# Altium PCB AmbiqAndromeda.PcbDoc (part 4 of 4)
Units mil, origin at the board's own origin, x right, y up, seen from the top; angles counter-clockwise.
Board outline 4055.04 x 2407.2 mil, 6 copper layers (Layer 1, Layer 2, Layer 3, Layer 4, Layer 5, Layer 6), stack 76.457 mil thick; 255 components, 215 nets, 1186 pads, 683 vias.
Unrouted connection lines stored in the file: 258.
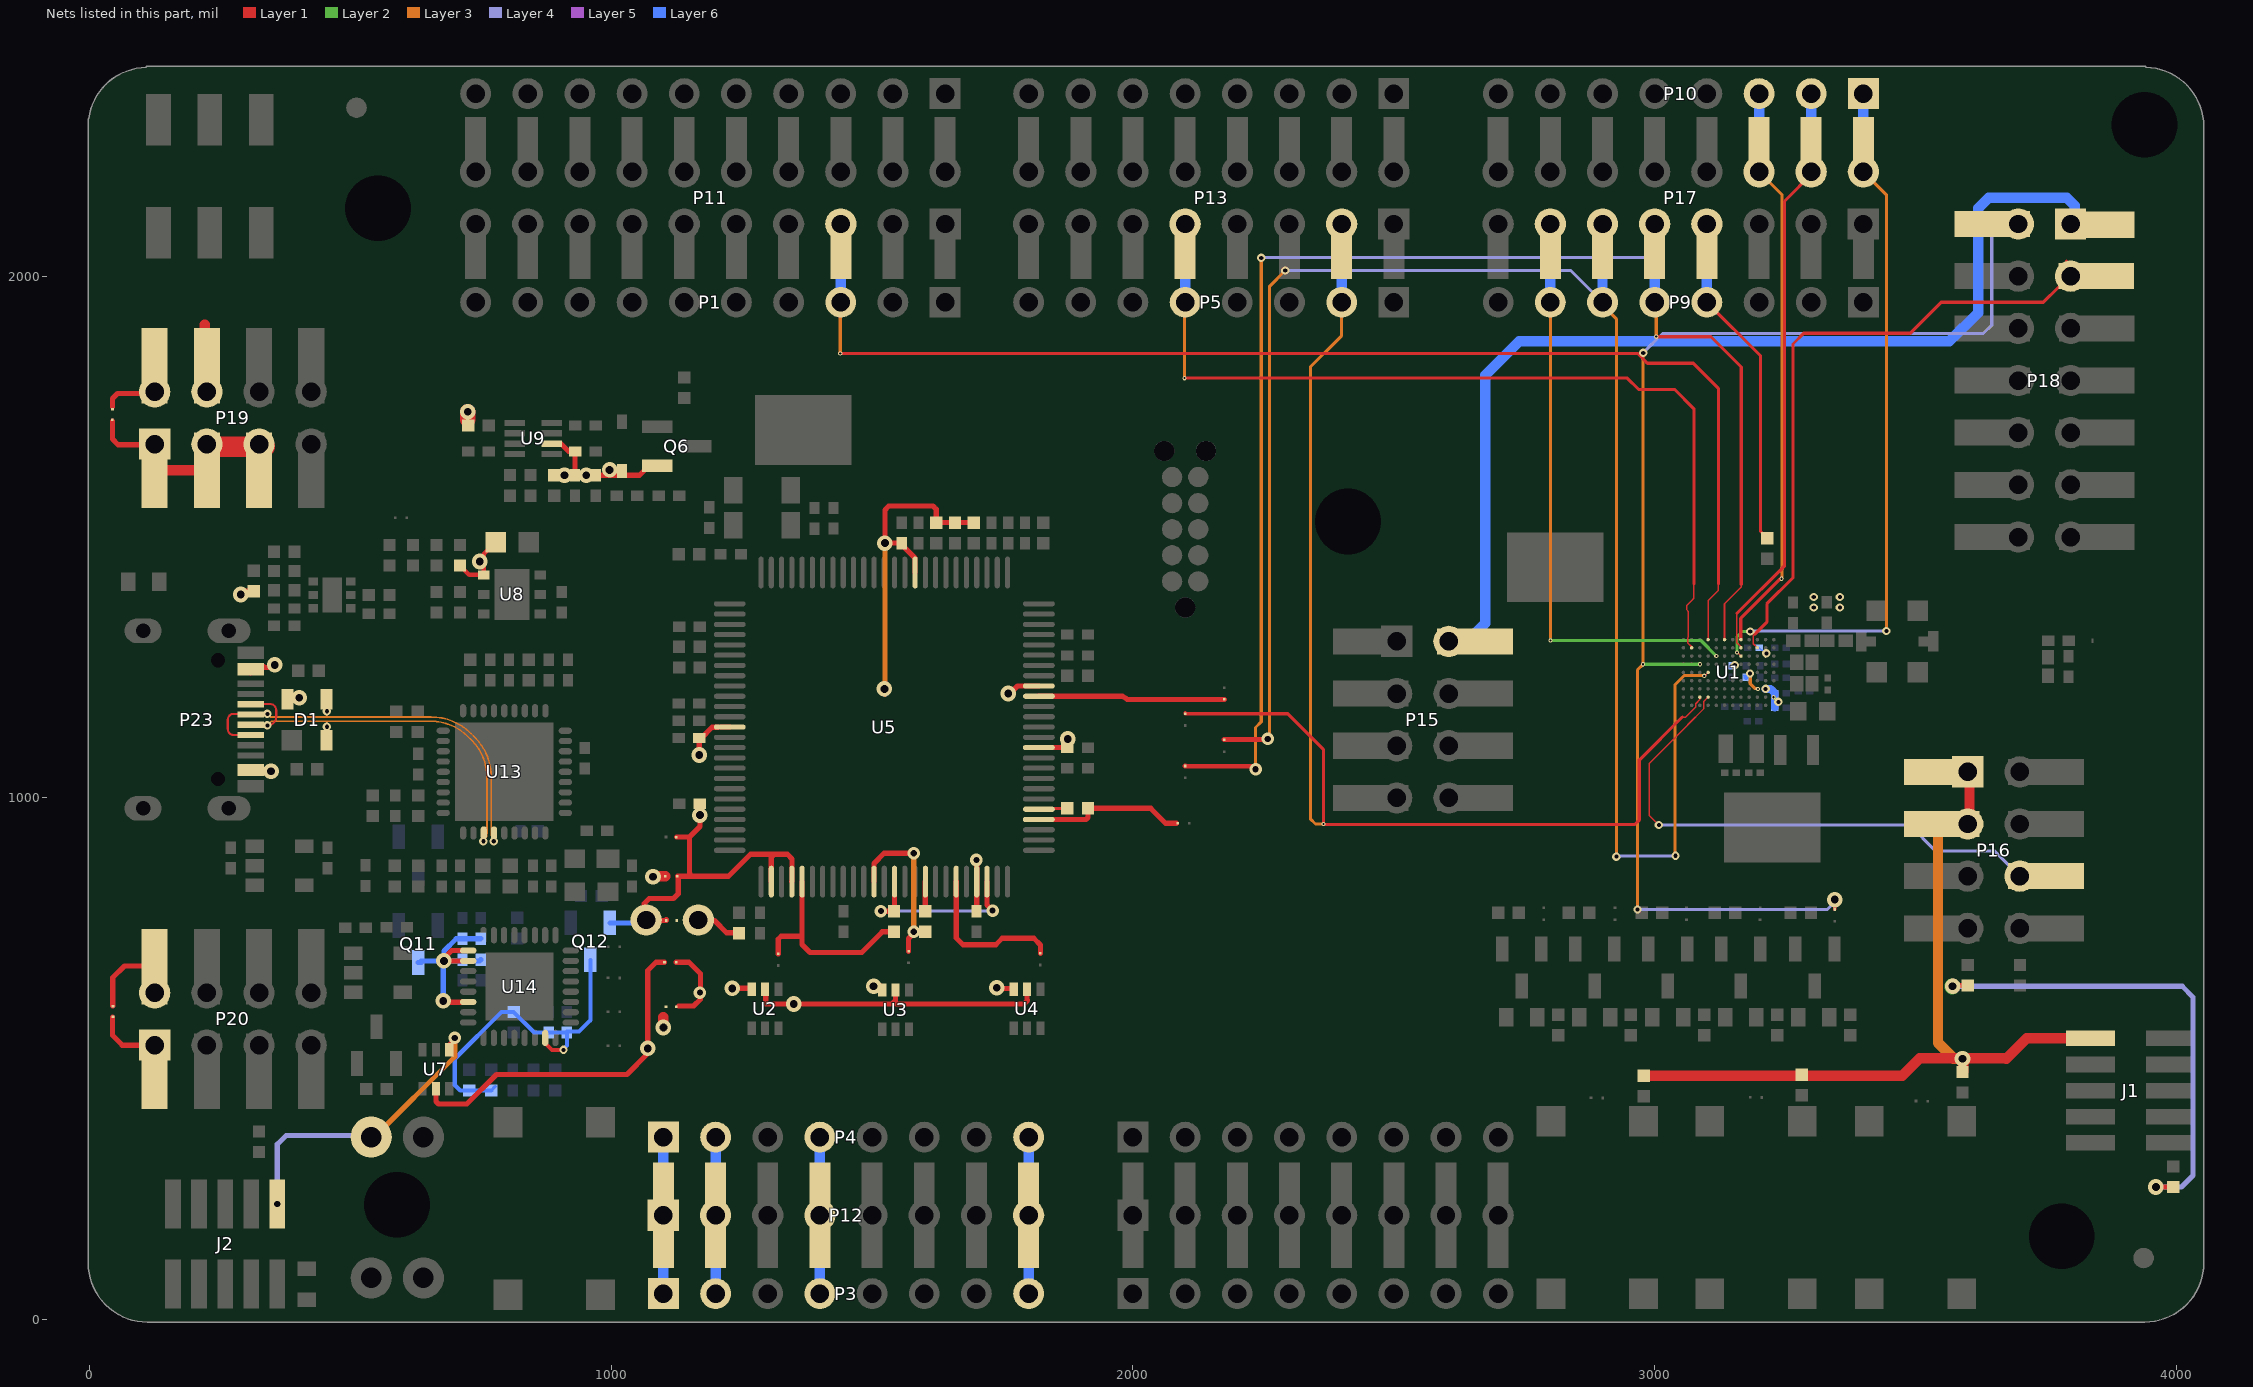
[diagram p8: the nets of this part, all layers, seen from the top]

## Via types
v1: diameter 30, hole 15, Layer 1 to Layer 6, tented both sides, 227 vias
v2: diameter 8, hole 4, Layer 1 to Layer 2, tented both sides, 113 vias
v3: diameter 8, hole 4, Layer 2 to Layer 3, tented both sides, 98 vias
v4: diameter 24, hole 12, Layer 1 to Layer 6, tented both sides, 91 vias
v5: diameter 16, hole 8, Layer 3 to Layer 4, tented both sides, 71 vias
v6: diameter 8, hole 4, Layer 5 to Layer 6, tented both sides, 26 vias
v7: diameter 16, hole 8, Layer 1 to Layer 6, tented both sides, 25 vias
v8: diameter 8, hole 4, Layer 4 to Layer 5, tented both sides, 20 vias
v9: diameter 8, hole 4, Layer 1 to Layer 2, 4 vias
v10: diameter 8, hole 4, Layer 2 to Layer 3, 4 vias
v11: diameter 16/16/16/16/16/16 (per signal layer), hole 8, Layer 1 to Layer 6, tented both sides, 2 vias
v12: diameter 24/0/0/24/24/24 (per signal layer), hole 12, Layer 1 to Layer 6, tented both sides, 1 vias
v13: diameter 30/0/0/30/30/30 (per signal layer), hole 15, Layer 1 to Layer 6, tented both sides, 1 vias

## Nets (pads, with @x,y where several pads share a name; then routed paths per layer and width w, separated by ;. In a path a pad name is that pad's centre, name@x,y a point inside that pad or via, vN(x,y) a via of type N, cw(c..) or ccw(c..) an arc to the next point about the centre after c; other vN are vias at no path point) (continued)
SWO_NCE71_CT21_TX0_RX0_TX1_RX1_GP71: P10.3 P17.6 U1.J5 | length 1112.9
  Layer 1 w3: U1.J5@3164.99,1303.77 U1.J5@3165.32,1303.45
  Layer 1 w6: U1.J5@3164.99,1303.77 3164.99,1344.14 3240.86,1420 v2(3242.93,1420)
  Layer 3 w6: P17.6@3200,2200 3244,2156 v3@3244,1420
  Layer 6 w6: P17.6@3200,2200 P17.6@3214.51,2200
  Layer 6 w20: P17.6@3200,2200 P10.3@3200,2349.99
  other v3: 3242.93,1420
SWO_NCE72_CT22_TX0_RX0_TX1_RX1_GP72: P10.2 P17.4 U1.H5 | length 1150.5
  Layer 1 w3: 3157.49,1353.49 3157.49,1312.02 3157.47,1297.53 3163.76,1291.24 3163.76,1290.25 3165.32,1288.7 U1.H5@3165.32,1287.7
  Layer 1 w6: 3157.49,1353.49 3249,1445 3249,2144 3305,2200 P17.4@3300,2200
  Layer 6 w6: P17.4@3300,2200 P17.4@3305,2200
  Layer 6 w10: P17.4@3289,2203 3292,2200 P17.4@3300,2200
  Layer 6 w20: P17.4@3289,2203 3300,2214 P10.2@3300,2349.99
SWO_NCE73_CT23_CTS0_RTS0_CTS1_RTS1_GP73: P10.1 P17.2 U1.G5 | length 1387.7
  Layer 1 w3: v2(3158,1279) 3158.27,1279 U1.G5@3165.32,1271.95
  Layer 2 w3: v2@3157.46,1279 v2(3158,1279)
  Layer 2 w6: v2@3157.46,1279 3157.46,1308.46 3168,1319 v3(3183,1319)
  Layer 3 w6: P17.2@3400,2200 3444,2156 v5(3444,1320)
  Layer 4 w6: v3(3183,1319) 3184,1320 v5(3444,1320)
  Layer 6 w6: P10.1@3400,2349.99 3405.01,2349.99 P10.1@3406,2349
  Layer 6 w20: P17.2@3400,2200 3400,2343 P10.1@3406,2349
  other v5: 3183,1319
TCKin: R6.1 SB7.1 U5.5 | length 395.4
  Layer 1 w10: SB7.1@1320,701.19 1320,729.14 1325.86,735 1365.89,735 ; U5.5@1365.89,839.53 1365.89,735 ; R6.1@1542,743.32 1519.57,743.32 1480.18,703.93 1381.07,703.93 1365.89,719.11 1365.89,735
TCKout: R6.2 U5.14 U5.23 | length 352.2
  Layer 1 w10: v4@1523.37,783.74 1524.42,782.69 R6.2@1542,782.69 1543.05,783.74 U5.14@1543.05,839.53 ; U5.23@1720.22,839.53 1720.22,794.78 v4(1731,784)
  Layer 5 w10: v4@1730.21,783.21 v4(1731,784) v4@1732,785
  Layer 4 w6: v4(1516.9,783.21) v4@1730.21,783.21
TDOin: SB10.1 U5.20 | length 301.6
  Layer 1 w10: U5.20@1661.17,839.53 1661.17,731.3 1673.98,718.48 1736.98,718.48 1749.57,731.07 1809.93,731.07 1823,718 ; SB10.1@1822.57,702.18 1822.57,717.77
TMSin: R7.1 SB8.1 U5.12 | length 334.4
  Layer 1 w10: U5.12@1503.68,839.53 1503.68,874.55 1523.14,894 v4(1580,894) ; SB8.1@1570,706.19 1570,730.46 1579.68,740.14 v4(1579.68,743.32) R7.1@1602,743.32
  Layer 3 w10: v4(1579.68,743.32) v4@1579.68,894.89
TMSout: R7.2 U5.17 | length 56.9
  Layer 1 w10: R7.2@1602,782.69 1602,839.42 U5.17@1602.11,839.53
TRESin: R9.1 SB9.1 U5.29 | length 295.2
  Layer 1 w10: U5.29@1819.63,958.62 1910.12,958.62 1913.68,962.19 R9.1@1913.68,980 2034,980 2062.49,951.51 SB9.1@2083.7,951.51
TRESout: R9.2 U5.30 | length 55.4
  Layer 1 w6: U5.30@1819.63,978.31 1822.61,978.31 1824.3,980 R9.2@1874.31,980
TRG1_NCE36_RX1_32K_CTS1_CTS0_PDMD_GP36: P9.7 P17.13 U1.G8 | length 1133.2
  Layer 1 w6: P9.7@2800,1950 P9.7@2802.02,1947.98
  Layer 2 w6: v3(2800,1302) 2800,1303 2800.5,1303.5 2802,1302 3088.02,1302 v2(3118.07,1271.95)
  Layer 3 w6: v3(2800,1302) P9.7@2800,1950
  Layer 6 w10: P9.7@2800,1950 P9.7@2800,1966
  Layer 6 w20: P9.7@2800,1966 P17.13@2800,2100
TRG2_NCE37_RTS0_SCCIO_TX1_PDMC_CT29_GP37: P9.6 P17.11 SB13.2 U1.E9 | length 3383
  Layer 1 w3: v2(3095,1234) 3095.87,1234 U1.E9@3102.33,1240.45 U1.E9@3103.03,1241.16
  Layer 1 w6: P17.11@2891.31,2103 2894.31,2100 P17.11@2900,2100
  Layer 1 w10: SB13.2@2174.63,1111.85 v4@2256.53,1111.85
  Layer 2 w3: v2(3095,1234) v3@3095.87,1234
  Layer 3 w6: v4(2258.24,1113) 2262,1116.76 2262,1981 v5(2292,2011) ; P9.6@2900,1950 2900,1944.69 2926.5,1918.19 v5(2926.5,887.5) ; v5(3040,889) 3039,890 3039,1217 3056.71,1234.71 3094.29,1234.71 v2(3095,1234)
  Layer 4 w6: v5(2292,2011) 2839,2011 P9.6@2900,1950 ; v5(2926.5,887.5) 2929,885 2931,887 2932,886 2935,889 v5(3040,889)
  Layer 6 w20: P9.6@2900,1950 P17.11@2900,2100 P17.11@2900,2101.5
  other v3: 3095,1234
TRIG3_NCE38_CTS0_M3MOSI_RX1_GP38: P9.5 P17.9 SB14.2 U1.J7 | length 2878.9
  Layer 1 w3: U1.J7@3133.82,1303.45 3133.82,1372 3166,1404.18 3166,1409
  Layer 1 w6: v2(3003,1884) 3108,1884 3166,1826 3166,1409
  Layer 1 w10: SB14.2@2100.12,1061.19 2230.14,1059.95 v4(2235,1055)
  Layer 5 w10: P17.9@3000,2100 P17.9@3003,2097
  Layer 3 w3: P9.5@2999,1944 3000,1945 P9.5@3000,1950
  Layer 3 w6: v4(2235,1055) 2235,1135 2246,1146 v5(2246,2035) ; P9.5@3000,1950 3003,1947 v2(3003,1884)
  Layer 4 w6: v5@2246,2036 2983,2036 3003,2056 P17.9@3003,2097
  Layer 6 w3: P9.5@3000,1950 P9.5@3000.33,1950
  Layer 6 w20: P9.5@3000,1950 P17.9@3000,2100
  other v3: 3003,1884
TX0_NCE22_CT12_PDMC_EXLF_MSPI0_SWO_GP22: P5.2 P13.3 SB11.2 U1.B10 | length 2541.7
  Layer 1 w3: 3053,1155 3059.47,1155 3078.68,1174.21 3078.68,1180.66 3086.58,1188.56 U1.B10@3086.58,1193.21
  Layer 1 w6: SB11.2@2100,1163.3 SB11.2@2100.12,1163.18 ; SB11.2@2100.12,1161.19 2296.81,1161.19 2365,1093 v3(2365,950) 2366,949 2962,949 2970.5,957.5 2970.5,1072.5 3053,1155
  Layer 3 w6: v3(2365,950) 2350,950 2340.01,959.99 2340.01,1826.01 2400,1886 P5.2@2400,1950
  Layer 6 w6: P5.2@2399,1950 P5.2@2399,1953 ; P5.2@2400,1950 P5.2@2408,1942
  Layer 6 w20: P5.2@2400,1950 2400.16,1950.16 P13.3@2400.16,2100
  other v2: 2365,950
TX0_NCE48_CT28_M5SCL_M5SCK_GP48: P5.5 P13.9 U1.H11 | length 1791.1
  Layer 1 w3: U1.H11@3070.83,1287.7 3070.83,1289.67 3062.98,1297.51 3062.98,1306.7 3064.5,1308.21 3064.5,1357.5 3061.75,1360.25 3061.75,1369.27 3066.97,1374.5 3067.11,1374.5 3071.5,1378.89 3071.5,1379.03 3075,1382.53 3075,1410
  Layer 1 w6: v2(2098.5,1804.5) 2947.5,1804.5 2969,1783 3038,1783 3075,1746 3075,1410
  Layer 2 w3: P5.5@2100,1950 P5.5@2100.16,1950
  Layer 3 w6: v2(2098.5,1804.5) 2099,1805 P5.5@2099,1939
  Layer 6 w3: P5.5@2097,1956 2100,1953 P5.5@2100,1950
  Layer 6 w6: P5.5@2097,1947 P5.5@2100,1950 ; P5.5@2097,1950 P5.5@2097,1956
  Layer 6 w10: P5.5@2097,1947 2097,1941 P5.5@2099,1939
  Layer 6 w20: P5.5@2097,1941 2100.16,1944.16 P13.9@2100.16,2100
  other v3: 2098.5,1804.5
TX0_TX1_CT25_M4SCL_M4SCK_GP39: P9.4 P17.7 R5.1 | length 650.4
  Layer 1 w6: P9.4@3100,1950 3203,1847 3203,1510.69 R5.1@3216,1497.69
  Layer 6 w20: P9.4@3100,1950 P17.7@3100,2100
TX1_M1MOSI_NCE10_PDMC_RTS1_GP10: P18.2 SB23.1 U1.F10 | length 2518.6
  Layer 1 w3: P18.2@3645.5,2098.48 P18.2@3647.02,2100
  Layer 1 w6: SB23.1@3345,786.19 v1(3345,805)
  Layer 2 w6: v3(2977.8,1256.2) v2(3086.58,1256.2)
  Layer 3 w6: v5(2967,786) 2967,1245.4 v3(2977.8,1256.2) 2977.8,1852.8 v5(2978,1853)
  Layer 4 w6: v5(2967,786) 3331,786 3345,800 v1(3345,805) ; v5(2978,1853) 3015,1890 3630,1890 3646,1906 3646,2089 3657,2100 P18.2@3697.02,2100
TX1_NCE24_MSPI8_CTS0_CT21_32K_SWO_GP24: P16.6 U1.B9 | length 1032.2
  Layer 1 w3: v2(3008,948) 2989.5,966.5 2989.5,1065.94 3063.45,1139.89 3063.45,1140.44 3094.42,1171.42 3094.42,1185.31 U1.B9@3102.33,1193.21
  Layer 4 w6: v2(3008,948) 3489,948 3539,898 3652,898 P16.6@3700,850
  other v3: 3008,948
  other v5: 3008,948
TX1_NCE42_CT16_M3SCL_M3SCK_GP42: P1.3 P11.5 U1.J9 | length 2459.8
  Layer 1 w3: U1.J9@3102.33,1303.67 3102.33,1377.99 3122,1397.67 3122,1410
  Layer 1 w6: v2(1439,1852) 2967,1852 2986,1833 3074,1833 3122,1785 3122,1410
  Layer 3 w6: v2(1439,1852) 1439,1921.97 1437,1923.97 1445.3,1932.27 1433.78,1943.78 P1.3@1440,1950
  Layer 6 w20: P1.3@1440,1950 P11.5@1440,2100
  other v3: 1439,1852
TxD: SB12.1 U5.41 | length 357.2
  Layer 1 w10: U5.41@1819.63,1194.85 1979.83,1194.85 1989.08,1188.81 SB12.1@2175,1188.81
TXEN: P18.3 U1.H3 | length 1232.1
  Layer 1 w3: 3188.97,1306.7 3188.97,1295.54 U1.H3@3196.81,1287.7 ; 3188.99,1306.72 3188.99,1311 3192,1314
  Layer 1 w6: 3192,1314 3206.84,1328.84 ; 3206.91,1328.77 3215,1336.86 3215,1372 3265,1422 3265,1870 3285.5,1890.5 3489.5,1890.5 3549,1950 3745,1950 3773,1978 3776.52,1978 3783,1984.48 P18.3@3783,1990 ; P18.3@3789,2021 3789,2029 ; P18.3@3810,2000 P18.3@3846.02,2000
USB_N: D1.2 P23.A7 P23.B7 U13.30 | length 712.8
  Layer 1 w4: P23.B7@309.27,1179.53 309.27,1180 346,1180 cw(c346,1168.06) 357.94,1168.06 357.94,1155.94 cw(c341,1155.94) v7(341,1139)
  Layer 3 w3.24: v7(341,1139) 349,1147 455,1147 ; v7(455,1136.5) 455,1147 ; v7@756,918 ccw(c741.8,932.2) 761.88,932.2 761.88,1039.7 ccw(c661.88,1039.7) 732.59,1110.41 725.29,1117.71 ccw(c654.58,1047) 654.58,1147 455,1147
  other v7: 755,917
USB_P: D1.3 P23.A6 P23.B6 U13.31 | length 750.5
  Layer 1 w4: P23.B6@309.27,1120.47 276.53,1120.47 cw(c276.53,1132) 265,1132 265,1150 cw(c276,1150) 276,1161 308.11,1161 cw(c308.11,1159.84) P23.A6@309.27,1159.84
  Layer 3 w3.24: v7(341,1161) 346.76,1155.24 455,1155.24 ; v7(455,1166.12) 455,1155.24 ; v11@776,918 cw(c790.2,932.2) 770.12,932.2 770.12,1039.77 ccw(c662.05,1039.77) 738.47,1116.18 731.09,1123.56 ccw(c654.61,1047.07) 654.61,1155.24 455,1155.24
  other v11: 775,917
V_FTDI: C71.2 C72.2 C73.2 C74.2 Q11.3 U14.25 U14.26 U14.30 | length 444.1
  Layer 1 w10: v1(678,611) 680.45,608.55 725.44,608.55 U14.30@725.79,608.9 ; v1(679.31,687.64) U14.26@725.79,687.64 725.79,687 U14.26@726,687 ; v1@683.75,688 cw(c683.75,692.44) 679.31,692.44 694.19,707.32 U14.25@725.79,707.32
  Layer 6 w8: C73.2@747.64,687.64 C73.2@749.69,689.69
  Layer 6 w10: Q11.3@630,684.57 635.57,684.57 636,685 636,686.83 636.81,687.64 678,687.64 v1(678,611) ; v1(679.31,687.64) 679.31,706.32 702.99,730 749.68,730 C72.2@750,730.31 ; v1@689.06,687.64 C73.2@747.64,687.64 ; C73.2@749.69,689.69 C73.2@750,690
V_FTDI_IO: C69.2 C70.2 Q12.3 R53.2 R54.2 R57.2 U14.7 | length 661.8
  Layer 1 w8: U14.7@873.43,540 873.43,530.35 886.77,517 v7(908.5,517)
  Layer 6 w6: R53.2@770,439.31 R53.2@777.9,447.21
  Layer 6 w8: R53.2@770,439.31 R57.2@728,439.31 710.69,439.31 700,450 700,500 789.69,589.69 R54.2@813,589.69 852.37,550.31 C70.2@880,550.31 C69.2@915,550.31 ; v7(908.5,517) 908.5,519.16 915,525.66 C69.2@915,550.31 ; Q12.3@960,689.57 960,574 938.28,552.28 915,552.28 C69.2@915,550.31
VBUS: D1.4 FB1.1 P23.A4 P23.A9 P23.B4 P23.B9 | length 141.8
  Layer 1 w10: v1@283.68,1396.32 FB1.1@315,1396.32 ; P23.B9@308.37,1239.65 P23.B9@309.27,1240.55 P23.B9@310.18,1241.46 ; P23.A9@309.28,1047.64 310.19,1048.54 334.28,1048.54 345.73,1060 350,1055.73 348,1053.73 v1(348,1051) ; P23.A4@309.27,1252.36 328.96,1252.36 329.87,1251.46 334.27,1251.46 335.72,1250 350,1250 v1(355,1255) ; v1(402,1192) v1@402,1197.97
  other v1: 290,1390
VDD_DBG: J1.1 P16.1 P16.3 R36.2 R37.2 R38.2 SB84.2 SB85.2 | length 1803.2
  Layer 1 w10: SB84.2@1124.49,684.88 1149.24,684.88 1171.12,663 1171.12,614.12 1158,601 1129.23,601 ; 3363,464.69 3363,467.69 ; 3674,500 3675,501
  Layer 1 w20: R36.2@2979,467.69 3363,467.69 3474.69,467.69 3508,501 v1@3600,501 ; P16.3@3550,950 P16.3@3600,950 3603.35,953.35 3603.35,1046.65 P16.1@3600,1050 P16.1@3550,1050 ; R38.2@3590,474.69 3591.81,476.5 3591.81,492.81 v1@3600,501 ; 3674,500 3713,539 J1.1@3835.23,539 ; 3675,501 v1@3600,501
  Layer 3 w20: v1(3590,500) 3574,500 3543,531 3543,934 3559,950 P16.3@3600,950
  other v4: 1170,627
VDD_EXP: P3.1 P3.2 P3.4 P4.1 P4.2 P4.4 P12.1 P12.2 P12.4 P15.2 P18.1 P20.2 SB16.2 | length 3063
  Layer 1 w10: SB16.2@44.64,601.36 44.64,655.64 67,678 P20.2@122,678 ; P15.2@2655.51,1300 2675,1300 P15.2@2677,1298
  Layer 6 w20: P3.1@1100,50 P12.1@1100,200 P4.1@1100,350 ; P3.2@1200,50 P12.2@1200,200 P4.2@1200,350 ; P3.4@1400,50 P12.4@1400,200 P4.4@1400,350 ; P15.2@2605.51,1300 2610.69,1305.18 2645.18,1305.18 2675,1335 2675,1810 2740,1875 3565,1875 3620,1930 3620,2130 3640,2150 3790,2150 3805,2135 3805,2105.96 P18.1@3797.02,2097.98 ; P18.1@3797.02,2100 P18.1@3797.02,2097.98 ; P18.1@3800,2095 P18.1@3797.02,2097.98
VDD_EXT_DBG: J2.1 pad.1 R86.2 SB6.1 TP1.1 U2.6 U3.6 U4.6 U7.1 | length 750
  Layer 1 w10: U7.1@689.59,517.4 692.46,520.28 692.46,528.68 700,536.21 v4(700,540) ; pad.1@1160,765 1197.65,765 1221.16,741.49 1236.9,741.49 R86.2@1242.11,736.28 ; v1@1235,635 U2.6@1267.83,635 ; v1@1503,639.53 1516.54,639.53 1519.41,636.65 U3.6@1519.41,631.73 ; v1(1739,636) 1740.23,634.77 1770.2,634.77 U4.6@1771.39,633.58
  Layer 3 w10: TP1.1@540,350 546,350 700,504 v4(700,540)
  Layer 4 w10: v4(360,221.77) 360,336 377,353 514,353 511,350 TP1.1@510,350
  other v1: 1232,635 1503,639
VDD_MCU: C1.2 C2.2 C3.2 C4.2 C5.2 P19.2 R79.1 SB15.2 SB85.1 U1.B1 U1.C2 U1.C3 U1.F6 U1.G2 | length 358.8
  Layer 1 w3: U1.F6@3149.57,1256.2 3149.8,1256.2 U1.F6@3150.28,1255.72 ; U1.F6@3151.52,1254.5 v6(3153.5,1254.5) ; U1.C3@3196.59,1209.18 U1.C3@3196.81,1208.96 ; U1.G2@3212.56,1271.95 3213.27,1272.66 3213.27,1275.17 v2@3212.72,1275.72
  Layer 1 w10: 44.04,1749.6 44.04,1765.57 53.47,1775 107,1775 P19.2@116.5,1784.5 ; P19.2@123,1778 125,1780 P19.2@125,1828.25 ; R79.1@720,1710 R79.1@723.9,1713.9
  Layer 1 w20: v1(1100,560) 1100,580
  Layer 1 w30: R79.1@725,1725 v1(725,1740)
  Layer 5 w3: P19.2@123,1781 125,1779 P19.2@125,1778.25
  Layer 2 w3: v3@3212,1277 3212.25,1277.25 3212.5,1277 v2(3214,1277)
  Layer 2 w6: v2(3228,1193) v6(3237,1184)
  Layer 3 w3: v3@3150.01,1253 3151.51,1254.5 v6(3153.5,1254.5) v3@3152,1253 ; v5@3212.88,1277.13 3213,1277 v2(3214,1277)
  Layer 3 w6: v5@3182.66,1238.55 3183.05,1238.95 3183.05,1218.91 3192.58,1209.38 3197.62,1209.38 v2(3198,1209)
  Layer 4 w3: v5@3151.51,1254.5 3150.01,1253 3151.52,1254.5 v6(3153.5,1254.5)
  Layer 4 w6: v8@3182.18,1239 v5(3182.62,1238.55)
  Layer 6 w3: C2.2@3146.02,1255 C2.2@3146.24,1254.78 ; C2.2@3148,1253.02 3148,1252.24 C2.2@3152.8,1247.44 ; C3.2@3170.91,1235.07 C3.2@3174.81,1230.8 ; C4.2@3197.66,1285.26 C4.2@3200.09,1287.7 3204.89,1282.9 3207.1,1282.9 3213,1277 v2(3214,1277) ; C1.2@3235.56,1178.59 3236.04,1179.07 3236.04,1183.04 v6(3237,1184)
  Layer 6 w10: C3.2@3175,1230.98 C3.2@3175,1231.76
  Layer 6 w15: v2(3212.56,1208.96) 3221.93,1208.96 3221.98,1209 C5.2@3229.98,1201 C1.2@3229.98,1173
  other v2: 3153.5,1254.5
  other v3: 3237,1184 3198,1209 3212.56,1208.96 3153.5,1254.5 3214,1277
  other v5: 3237,1184 3212.56,1208.96 3153.5,1254.5 3214,1277
  other v6: 3212.56,1208.96 3182.62,1238.55 3214,1277
  other v7: 3305,1365 3355,1365 3305,1385 3355,1385
  other v8: 3237,1184 3212.56,1208.96 3182.62,1238.55 3153.5,1254.5 3214,1277
VDD_MCU_TRACK: C80.1 C83.2 C84.2 D70.2 Q6.2 R1.1 R3.1 R82.2 SB84.1 U2.5 U3.5 U4.5 U7.5 U9.6 | length 2510.6
  Layer 1 w10: U7.5@664,442.6 664,418 668.86,413.14 723.14,413.14 780,470 1030,470 1070,510 1070,669.32 1085.68,685 SB84.1@1102.11,685 ; U9.6@885.93,1679.06 903.39,1679.06 918.55,1663.9 C80.1@930.82,1663.9 930.82,1618.9 C84.2@930.5,1618.58 ; R82.2@890.5,1618.58 v1(910.5,1618.58) C84.2@930.5,1618.58 ; Q6.2@1088.1,1636.5 1072.37,1636.5 1054.45,1618.58 C83.2@970.5,1618.58 v1(952,1618.58) C84.2@930.5,1618.58 ; U2.5@1294.84,633.58 1296.32,632.11 1296.32,605 1296.44,604.88 1538.2,604.88 ; U3.5@1545,631.73 1545,611.68 1538.2,604.88 ; 1796.98,614.02 U4.5@1796.98,633.58 ; 1798,612 1790.88,604.88 1538.2,604.88 ; v1(3571,639) 3572.31,640.32 R1.1@3600,640.32 ; v1(3960.68,254.32) R3.1@3994,254.32
  Layer 2 w30: v1@3570.5,638.5 v1(3571,639)
  Layer 4 w10: v1(3571,639) 4011,639 4032,618 4032,276.57 4009.75,254.32 v1(3960.68,254.32)
  other v1: 1070,520 1350,605 997,1628.78
VDD_PS: P19.1 P19.3 P19.5 P20.1 SB5.1 SB15.1 SB16.1 | length 666.4
  Layer 1 w10: SB15.1@43.96,1722.45 43.96,1687.71 54.67,1677 P19.1@123,1677 ; SB16.1@44.01,579.65 44.01,544.99 63,526 126,526 125,525 P20.1@125,476.25
  Layer 1 w20: P19.1@123,1677 125,1675 P19.1@125,1628.25 P19.3@225,1628.25 ; P19.5@325,1628.25 325,1662 P19.5@336,1673 ; v1@1082,850 SB5.1@1103.81,850
  Layer 1 w40: P19.3@225,1628.25 225,1668 230,1673 P19.5@336,1673
  other v1: 1080,849
VDD_PS_LDO: C33.2 P19.4 R22.2 U8.4 | length 268.9
  Layer 1 w8.59: P19.4@221,1839 225,1835 P19.4@225,1828.25 P19.4@225,1778.25 ; R22.2@710,1445.31 727.91,1427.4 U8.4@755.87,1427.4 755.87,1467.36 C33.2@778.5,1490
  Layer 1 w20: P19.4@221,1839 221,1907
  Layer 3 w8.59: P19.4@225,1765 P19.4@225,1778.25
  other v1: 748,1453
VDDIO: C15.2 C16.2 C17.2 C18.2 C49.2 pad.2 Q12.2 R10.2 R11.2 R12.1 SB4.2 SB5.2 SB6.2 U5.2 U5.4 U5.22 U5.36 U5.42 U5.60 U5.88 | length 1741.6
  Layer 1 w10: SB6.2@1104.84,767.13 1105.53,766.44 SB6.2@1105.53,765.04 1074.24,765.04 1063,776.28 1063,797 1073,807 1119.3,807 1128.3,816 SB5.2@1128.3,850 ; SB4.2@1125,924.96 1150,924.96 ; SB5.2@1127.5,850 1127.38,849.88 1128.18,849.88 SB5.2@1128.3,850 ; SB5.2@1127.78,850 SB5.2@1128.3,850 ; v1(1168.69,1082.16) C15.2@1168.69,1115 1172.81,1115 1193.31,1135.5 U5.88@1204,1135.5 ; C49.2@1169.69,989 1169.69,975 1170,975 v1(1170,966.98) 1170,958.96 1170,944.96 1150,924.96 ; U5.88@1210.22,1135.79 U5.88@1227.11,1135.79 ; U5.2@1306.83,839.53 1306.83,885.83 1313,892 ; U5.4@1346.2,839.53 1346.67,839.99 1346.67,883 1337.67,892 1313,892 ; U5.60@1582.43,1432.05 1582.43,1460 1582,1460 1557,1485 C16.2@1557,1488.31 v1(1524.49,1488.31) 1524.49,1551.97 1532.06,1559.54 1616.52,1559.54 1623,1553.07 R12.1@1623,1527.69 R11.2@1695,1527.69 ; C18.2@1700,782.69 1700.54,783.22 U5.22@1700.54,839.53 1700.54,880.46 v4(1700,881) ; v1(1761,1200) 1764,1200 1778.53,1214.53 U5.42@1819.63,1214.53 ; U5.36@1819.63,1096.42 1873.89,1096.42 C17.2@1874.31,1096 ; SB5.2@1128.3,850 1155,850 ; 1150,924.96 1150,855 1155,850 ; 1155,850 1225,850 1267,892 1313,892
  Layer 3 w10: v1@1524.49,1198.51 v1(1524.49,1488.31)
  Layer 6 w10: Q12.2@997.4,760.43 1003.57,760.43 1004,760 1061,760 pad.2@1067,766 ; v1(1523.5,1209) 1523.5,1199.5 v1@1524.49,1198.51
  other v1: 1875,1112.93
VIN: P3.8 P4.8 P12.8 | length 300
  Layer 6 w20: P3.8@1800,50 P12.8@1800,200 P4.8@1800,350
pads on no net: J1.7 J1.8 J2.7 J2.8 J3.7 J3.9 J3.MH P2.9 P2.10 P11.18 P11.20 P21.1 P21.3 P22.1 P22.3 P23.A8 P23.B8 P23.MH@246.38,1036.22 P23.MH@246.38,1263.78 SW1.3 SW1.6 U5.7 U5.8 U5.11 U5.13 U5.15 U5.16 U5.18 U5.24 U5.25 U5.28 U5.31 U5.32 U5.33 U5.37 U5.44 U5.48 U5.49 U5.50 U5.58 U5.62 U5.63 U5.64 U5.65 U5.66 U5.67 U5.68 U5.69 U5.70 U5.71 U5.84 U5.85 U5.86 U5.90 U5.91 U5.92 U5.93 U5.94 U5.95 U5.96 U5.97 U5.98 U5.100 U6.3 U8.3 U11.4 U12.4 U13.6 U13.7 U13.8 U13.9 U13.13 U13.17 U13.18 U13.19 U13.20 U13.21 U14.11 U14.12 U14.13 U14.14 U14.15 U14.16 U14.17 U14.29 U14.31

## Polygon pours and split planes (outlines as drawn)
HUB_3.3V on Layer 5 "HUB_3.3V_POWER_PLANE" (solid, remove dead copper, pour order 101): 445,887.5 535.5,887.5 536,887 536,795 572.77,795 585,782.77 585,740 600,725 685,725 695,735 695,915 945,915 945,940 1080,940 1080,1380 904,1380 904,1280 510,1280 510,980 445,980
5V_USB on Layer 5 "5V_USB_POWER_PLANE" (solid, remove dead copper, pour order 93): 425,795 525,795 525,875 425,875 425,993 500,993 500,1280 515,1295 891,1295 891,1380 840,1380 840,1700 1020,1700 1040,1680 1040,1560 1050,1550 1078.38,1550 1200,1671.62 1200,1840 770,1840 770,1750 680,1750 680,1840 560,1840 560,1567 778,1567 778,1416 670,1416 669,1417 669,1478 667,1480 560,1480 470,1480 460,1490 460,1710 450,1720 280,1720 270,1710 270,1610 260,1600 180,1600 170,1590 170,930 170,480 170,430 10,430 10,20 960,20 980,40 980,130 990,140 1550,140 1550,260 390,260 280,370 280,470 280,795
AT_3.3V on Layer 5 "AT_3.3V_POWER_PLANE" (solid, remove dead copper, pour order 67): 569,780.25 569,709 704,709 704,900 958,900 958,930 1272.8,930 1290,947.2 1290,1401.05 1318.92,1429.96 2030,1430.14 2030,1440 2160,1440 2160,1260 1410,1260 1380,1230 1380,800 1060,800 1060,815 920,815 920,282 407,282 303.55,385.45 303.55,780.25 523.55,780.25
VDD_EXP on Layer 5 "VDD_EXP_POWER_PLANE" (solid, remove dead copper, pour order 79): 3600,1170 3600,2165 3910,2165 3910,1470 3835,1470 3835,675 4040,675 4040,30 2850,30 2840,20 1010,20 1010,120 1580,120 1580,260 3690,260 3690,1170 3620,1170
GND on Layer 5 "Layer 5-GND" (solid, remove dead copper, pour order 119): 3384.24,2191.73 3384.24,1336.73 3264.24,1336.73 3264.24,1756.73 2494.24,1756.73 2494.24,1361.73 2494.24,956.73 2104.24,956.73 2104.24,611.73 1649.24,611.73 1649.24,481.73 3469.24,481.73 3479.24,491.73 3479.24,1151.73 3499.24,1171.73 3574.24,1171.73 3579.24,1176.73 3579.24,2191.73 3899.24,2191.73 3899.24,1491.73 4099.24,1491.73 4099.24,2391.73 -0.76,2391.73 -0.76,2191.73
VDDIO on Layer 5 "VDDIO_POWER_PLANE" (solid, remove dead copper, pour order 69): 1090,1360 1090,940 1265.72,940 1280,954.28 1280,1414.28 1310,1444.28 2170,1444.28 2170,1374.28 2170,1244.28 1420,1244.28 1390,1214.28 1390,784.28 1033.8,784.28 1033.8,805.78 1032.3,804.28 930,804.28 930,654.28 1530,654.28 1530,830 1910,830 1910,1124.28 2280,1124.28 2280,1604.28 1334.28,1604.28
VBUS on Layer 5 "VBUS_PWER_PLANE" (solid, remove dead copper, pour order 61): 260,1410 450,1410 464.9,1395.1 464.9,1044.9 450,1030 270,1030 250,1050 250,1400
VDD_DBG on Layer 5 "Layer 5-VDD_DBG" (solid, pour order 73): 930,640 1290,640 1290,460 3470,460 3500,490 3500,1130 3520,1150 3670,1150 3670,280 930,280
VDD_MCU_TRACK on Layer 5 "VDD_MCU_TRACK_POWER_PLANE" (solid, remove dead copper, pour order 71): 2085,970 2085,625 1635,625 1635,480 1315,480 1315,635 1545,635 1545,815 1925,815 1925,820 1925,1110 2300,1110 2300,1620 2200,1620 1330,1620 1110,1400 850,1400 850,1690 1010,1690 1020,1680 1020,1530 1080,1530 1220,1670 1220,1749.71 2470,1749.71 2470,970
VDD_PS on Layer 5 "VDD_PS_POWER_PLANE" (solid, remove dead copper, pour order 65): 250,1720 260,1710 260,1620 250,1610 170,1610 160,1600 160,480 140,460 30,460 10,480 10,1700 30,1720
VDD_MCU on Layer 5 "VDD_MCU_POWER_PLANE" (solid, remove dead copper, pour order 75): 690,1850 690,1760 760,1760 760,1850 1210,1850 1210,1770 3280,1770 3280,1345 3370,1345 3370,2170 1930,2170 20,2170 20,1730 140,1730 160,1750 160,1850
VDD_PS_LDO on Layer 5 "VDD_PS_LDO_POWER_PLANE" (solid, remove dead copper, pour order 59): 550,1558 770,1558 770,1427 677,1427 677,1490 480,1490 470,1500 470,1720 460,1730 177.04,1730 170,1737.05 170,1830 180,1840 540,1840 550,1830
GND on Layer 4 "Layer 4-No Net" (solid, remove dead copper, pour order 121): 0,2400 4100,2400 4100,0 0,0
VDD_MCU_TRACK on Layer 4 "VDD_MCU_TRACK_POWER_PLANE_L4" (solid, remove dead copper, pour order 85): 3890,470 3890,180 3920,150 3980,150 4000,170 4040,170 4040,617 1015,617 1015,470
VDD_PS on Layer 4 "VDD_PS_POWER_PLANE_L4" (solid, remove dead copper, pour order 77): 312.47,430 360,430 690,430 690,310 830,310 830,800 1107,800 1107,880 900,880 710,880 710,520 180,520 180,580 40,580 13,553 13,22.98 242,24.49 242,362.06
5V_USB on Layer 4 "5V_USB_POWER_PLANE_L4" (solid, remove dead copper, pour order 97): 1040,1690 2240,1690 2240,1390 1040,1390
VDD_EXT_DBG on Layer 4 "VDD_EXT_DBG_POWER_PLANE_L4" (solid, remove dead copper, pour order 87): 850,790.2 1820,790.2 1820,626 1005,626 1005,160.2 690,160.2 267,160.2 267,352.28 339.13,420.2 540,420.2 550,420.2 650,420.2 670,400.2 670,300.2 681.2,289 828.8,289 850,310.2
VDD_MCU on Layer 3 "VDD_MCU_POWER_PLANE_L3" (solid, remove dead copper, pour order 83): 10,2400.17 1140,2400.17 1140,500 950,500 950,740 10,740
VDD_EXP on Layer 3 "VDD_EXP_POWER_PLANE_L3" (solid, remove dead copper, pour order 81): 930,560 930,480 1160,480 1160,560 1450,560 1450,0 0,0 -10,-10 0,720 930,720
GND on Layer 3 "Layer 3-GND" (solid, remove dead copper, pour order 115): 1192.91,2405.43 4092.91,2405.43 4092.91,5.43 1492.91,5.43 1492.91,605.43 1192.91,605.43
GND on Layer 1 "Layer 1-GND" (solid, remove dead copper, pour order 111): 5.51,2398.19 4058.02,2398.19 4058.02,-1.81 5.51,-1.81
AT_VDDOUT on Layer 1 "AT_VDDOUT_POWER_PLANE_L1" (solid, remove dead copper, pour order 89): 1260,1400 1262.3,1397.7 1784.7,1397.7 1784.7,884.7 1780,880 1260,880
GND on Layer 6 "Layer 6-GND" (solid, remove dead copper, pour order 109): 9.64,2386.22 4109.64,2386.22 4109.64,-13.78 9.64,-13.78
VDD_MCU on Layer 6 "Layer 6-VDD_MCU" (solid, remove dead copper, pour order 105): 3100,1400 3375,1400 3375,1335 3250,1335 3250,1185 3100,1185
NetC38_2 on Layer 6 "Layer 6-NetC38_2" (solid, remove dead copper, pour order 107): 3229.79,1310.79 3244,1325 3375,1325 3375,1220 3330,1220 3330,1300 3230.55,1300 3229.79,1299.24
no net on Layer 6 "Layer 6-No Net" (solid, pour order 103): 3098,1354
GND on Layer 2 "Layer 2-GND" (solid, remove dead copper, pour order 113): 0,2400 4100,2400 4100,0 0,0

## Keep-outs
Keep-Out Layer:
  lines w5: 0.12,2186.96 0.12,2292 ; 0.12,2288.71 cw(c109.12,2290.72) 107.11,2399.72 ; 0.25,2186.58 0.25,104.25 ccw(c108.87,106.46) 111.08,-2.17 ; 107.22,2400 3938.99,2400 cw(c3938.91,2289.07) 4049.84,2288.99 4049.84,2186.99 ; 110.99,-2.17 111.17,-2.17 3941.47,-2.17 ; 3943.89,-2.11 ccw(c3941.47,106.41) 4049.99,108.83 4049.84,108.99 4049.84,2186.99 ; 4049.84,2186.99 4049.84,2186.99

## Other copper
Layer 1:
  rectangle net GND: 3320,1370 3340,1396.81
  rectangle net GND: 3671,1210 3835,1249.58
  rectangle net GND: 3390,1359.06 3550,1400.32
  rectangle net GND: 3390,1200 3550,1240.32
  rectangle net GND: 3790,1353 3834,1395
  rectangle net GND: 3794.29,1389.76 3833.66,1430.12
  pour cut-out: 1072.09,1308.13 1086,1308 1087.03,1198.19 1072,1198.19
  pour cut-out: 3834,1467.09 4050,1467 4050,677.16 3835.02,677
Layer 5:
  pour cut-out: 3833.84,1467.09 4049.84,1467 4049.84,677.16 3834.86,677
Layer 2:
  pour cut-out: 3833.84,1467.09 4049.84,1467 4049.84,677.16 3834.86,677
Layer 3:
  pour cut-out: 3834,1467.09 4050,1467 4050,677.16 3835.02,677
Layer 4:
  pour cut-out: 3834,1467.09 4050,1467 4050,677.16 3835.02,677
Layer 6:
  pour cut-out: 3834,1467.09 4050,1467 4050,677.16 3835.02,677

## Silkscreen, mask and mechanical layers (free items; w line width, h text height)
Top Overlay:
  drawing of 1720 lines, arcs and shapes, not listed
  text "VDD" at 3929.31,2089.55 h50
  text "10" at 3485.46,2085.48 h50
  text "28" at 3489.41,1987.48 h50
  text "TXEN" at 3929.16,1986.65 h50
  text "POWER" at 165,1969 h65
  text "ON" at 538.9,1942.85 h65
  text "16" at 3485.46,1889.48 h50
  text "30" at 3939.61,1889.95 h50
  text "8" at 728.55,1847.25 h50
  text "9" at 834.6,1847.75 h50
  text "6" at 1229.59,1847.27 h50
  text "7" at 1336.67,1847.76 h50
  text "42" at 1419.27,1847.27 h50
  text "43" at 1518.86,1847.27 h50
  text "44" at 1619.27,1847.38 h50
  text "45" at 1778.1,1847.5 h50
  text "46" at 1878.85,1847.5 h50
  text "22" at 2384,1847.5 h50
  text "23" at 2480.15,1847.5 h50
  text "27" at 3284.55,1847.45 h50
  text "5" at 1130.4,1846.7 h50
  text "47" at 1978,1846.45 h50
  text "48" at 2079.25,1847 h50
  text "49" at 2178.35,1847 h50
  text "26" at 2280,1847.15 h50
  text "12" at 2677.25,1846.25 h50
  text "36" at 2778.75,1846.25 h50
  text "38" at 2978.5,1846.25 h50
  text "39" at 3083.4,1846.25 h50
  text "40" at 3179.1,1847.1 h50
  text "25" at 3379.1,1847.1 h50
  text "37" at 2878.65,1845.4 h50
  text "VDD_MCU" at 94,1837.69 h50 r90
  text "3.3V" at 191,1837.64 h50 r90
  text "LV_EN" at 292.39,1837.6 h50 r90
  text "GND" at 393,1837.64 h50 r90
  text "GND" at 1055,1810 h50 r90
  text "15" at 3938.01,1788.2 h50
  text "18" at 3486.76,1784.93 h50
  text "ADCREF" at 955,1735 h50 r90
  text "14" at 3938.01,1689.6 h50
  text "19" at 3485.46,1685.63 h50
  text "Rev 1.0" at 2918,1596 h65
  text "AMA3B2EVB" at 2560,1595 h65
  text "17" at 3938.51,1586.75 h50
  text "GND" at 3461.91,1582.73 h50
  text "Apollo3 Blue Plus Evaluation Board" at 2554,1545 h65
  text "GND" at 392,1521 h50 r90
  text "NRST" at 3931.66,1486.9 h50
  text "GND" at 3464.61,1483.08 h50
  text "VDD_PS" at 290,1450 h50 r90
  text "VDD_PS" at 185,1448 h50 r90
  text "VDD_PS" at 96.16,1447 h50 r90
  text "1" at 2305,1291 h45
  text "VDD" at 2764.03,1291 h45
  text "0" at 2305,1191 h45
  text "2" at 2784.03,1191 h45
  text "NRST" at 2240.51,1091 h45
  text "GND" at 2759.03,1091 h45
  text "GND" at 3838.55,1036.4 h50
  text "VDD" at 3378.25,1034.15 h50
  text "4" at 2310.51,991 h45
  text "3" at 2783.52,991 h45
  text "GND" at 3836.9,939.85 h50
  text "VDD" at 3377.75,934.5 h50
  text "24" at 3850.45,839.3 h50
  text "41" at 3402.25,837.3 h50
  text "RoHS" at 2605.3,814.14 h60
  text "S" at 2071.7,740.29 h53
  text "E" at 2106.73,740.29 h53
  text "G" at 2137.6,740.29 h53
  text "G" at 2176.6,740.29 h53
  text "E" at 2216.9,740.29 h53
  text "R" at 2249.8,740.29 h53
  text "21" at 3403.1,738.25 h50
  text "20" at 3849.4,738.05 h50
  text "GND" at 390.14,686.35 h50 r90
  text "TM" at 2051,685 h45
  text "5V_USB" at 192.39,683.96 h50 r90
  text "AT_3.3V" at 288.39,683.96 h50 r90
  text "VDD_EXP" at 87,678 h50 r90
  text "Technology" at 2126,670 h67
  text "J-Link" at 1902.7,667.09 h67
  text "DEBUG" at 3827,628 h65
  text "www.segger.com" at 1905.9,621.79 h76
  text "IN" at 3886,577 h65
  text "SYSTEM" at 790,465 h65
  text "13" at 1971.97,452.99 h50
  text "29" at 2071.01,452.99 h50
  text "11" at 2168.56,452.99 h50
  text "31" at 2271.61,452.99 h50
  text "32" at 2369.81,452.99 h50
  text "33" at 2473.56,452.99 h50
  text "34" at 2573.56,452.99 h50
  text "35" at 2678.56,452.99 h50
  text "RESET" at 820,420 h65
  text "VDD" at 1110.31,420 h50 r90
  text "VDD" at 1215,420 h50 r90
  text "NRST" at 1310,419.97 h50 r90
  text "VDD" at 1415,420 h50 r90
  text "5V" at 1505.31,419.97 h50 r90
  text "GND" at 1605.98,419.97 h50 r90
  text "GND" at 1710.31,419.97 h50 r90
  text "VIN" at 1810,420 h50 r90
  text "GND" at 390,375 h50 r90
  text "5V_USB" at 192.99,307.63 h50 r90
  text "AT_3.3V" at 289.99,301.85 h50 r90
  text "VDD_PS" at 92.99,299.48 h50 r90
  text "DEBUG" at 71.28,65 h65 r90
  text "OUT" at 116.28,65 h65 r90
Bottom Overlay:
  circle w6: c940,2274 r30.41
  circle w6: c1039,2272 r30.41
  circle w6: c1135,2275 r30.41
  circle w6: c1645,2275 r30.41
  circle w6: c1545,2275 r30.41
  circle w6: c3000,2270 r30.41
  circle w6: c2900,2270 r30.41
  circle w6: c1445,2275 r30.41
  circle w6: c1235,2275 r30.41
  circle w6: c1800,2275 r30.41
  circle w6: c2100,2275 r30.41
  circle w6: c1340,2275 r30.41
  circle w6: c2400,2275 r30.41
  circle w6: c3200,2270 r30.41
  circle w6: c2800,2270 r30.41
  circle w6: c3400,2270 r30.41
  circle w6: c2200,2275 r30.41
  circle w6: c2300,2275 r30.41
  circle w6: c1900,2275 r30.41
  circle w6: c3100,2270 r30.41
  circle w6: c2000,2275 r30.41
  circle w6: c3300,2270 r30.41
  circle w6: c2700,2270 r30.41
  circle w6: c2500,2275 r30.41
  circle w6: c741.85,1875.75 r30.41
  circle w6: c2501.85,1875.75 r30.41
  circle w6: c3610,1712.5 r30.41
  circle w6: c841.85,1875.75 r30.41
  circle w6: c3610,1812.5 r30.41
  circle w6: c2199.15,464.65 r30.41
  circle w6: c2706.85,1870.75 r30.41
  circle w6: c3301.85,1870.75 r30.41
  circle w6: c2099.15,464.65 r30.41
  circle w6: c2001.85,1875.75 r30.41
  circle w6: c2690,1012.5 r30.41
  circle w6: c3101.85,1870.75 r30.41
  circle w6: c1901.85,1875.75 r30.41
  circle w6: c2499.15,464.65 r30.41
  circle w6: c2690,1212.5 r30.41
  circle w6: c3610,1912.5 r30.41
  circle w6: c3514,863.5 r30.41
  circle w6: c2420,1212.5 r30.41
  circle w6: c2299.15,464.65 r30.41
  circle w6: c3514,764.5 r30.41
  circle w6: c2301.85,1875.75 r30.41
  circle w6: c2420,1307.5 r30.41
  circle w6: c3885,1912.5 r30.41
  circle w6: c2201.85,1875.75 r30.41
  circle w6: c2004.15,464.65 r30.41
  circle w6: c3788,867.5 r30.41
  circle w6: c3885,1812.5 r30.41
  circle w6: c3401.85,1870.75 r30.41
  circle w6: c2806.85,1870.75 r30.41
  circle w6: c3201.85,1870.75 r30.41
  circle w6: c3788,763.5 r30.41
  circle w6: c2401.85,1875.75 r30.41
  circle w6: c2599.15,464.65 r30.41
  circle w6: c3885,1612.5 r30.41
  circle w6: c1341.85,1875.75 r30.41
  circle w6: c2101.85,1875.75 r30.41
  circle w6: c2699.15,464.65 r30.41
  circle w6: c3885,1712.5 r30.41
  circle w6: c1801.85,1875.75 r30.41
  circle w6: c1236.85,1875.75 r30.41
  circle w6: c2399.15,464.65 r30.41
  circle w6: c2420,1012.5 r30.41
  circle w6: c1446.85,1875.75 r30.41
  circle w6: c2901.85,1870.75 r30.41
  circle w6: c3001.85,1870.75 r30.41
  circle w6: c3610,2012.5 r30.41
  circle w6: c1546.85,1875.75 r30.41
  circle w6: c1646.85,1875.75 r30.41
  circle w6: c1136.85,1875.75 r30.41
  circle w6: c3610,2112.5 r30.41
  text "55" at 1466.45,2263.05 h50
  text "64" at 2420.8,2262.45 h50
  text "NC" at 760,2262 h50
  text "52" at 1155,2262 h50
  text "53" at 1257,2262 h50
  text "54" at 1362.75,2261.45 h50
  text "58" at 1820.05,2261.85 h50
  text "59" at 1922.05,2261.75 h50
  text "60" at 2022.05,2261.85 h50
  text "61" at 2122.05,2261.75 h50
  text "62" at 2222.05,2261.75 h50
  text "63" at 2322.05,2261.75 h50
  text "65" at 2520.35,2261.75 h50
  text "NC" at 862,2261 h50
  text "50" at 960,2261 h50
  text "56" at 1565.6,2260.9 h50
  text "57" at 1665,2260.55 h50
  text "51" at 1059,2259 h50
  text "66" at 2722.4,2257.85 h50
  text "67" at 2820.55,2257.85 h50
  text "69" at 3021.25,2256.2 h50
  text "70" at 3119.45,2257 h50
  text "71" at 3220.15,2256.2 h50
  text "73" at 3420.75,2257 h50
  text "72" at 3319.2,2255.35 h50
  text "68" at 2919.7,2254.5 h50
  text "10" at 3631.75,2098.05 h50
  text "VDD" at 3928.85,2098.05 h50
  text "VDD_MCU" at 141,2015.1 h50 r90
  text "28" at 3629.25,1999.85 h50
  text "TXEN" at 3951.3,1996.55 h50
  text "LV_EN" at 343,1951 h50 r90
  text "GND" at 442,1913.54 h50 r90
  text "3.3V" at 236,1909.17 h50 r90
  text "ADCREF" at 956.45,1908.05 h50 r90
  text "GND" at 1058.8,1908.05 h50 r90
  text "16" at 3632.55,1899.15 h50
  text "30" at 3905.55,1899.15 h50
  text "6" at 1246.4,1863.8 h50
  text "42" at 1468.3,1863.8 h50
  text "22" at 2422.65,1863.2 h50
  text "7" at 1350.6,1862.2 h50
  text "45" at 1821.9,1862.6 h50
  text "46" at 1923.9,1862.5 h50
  text "47" at 2023.9,1862.6 h50
  text "48" at 2123.9,1862.5 h50
  text "49" at 2223.9,1862.5 h50
  text "26" at 2323.9,1862.5 h50
  text "23" at 2522.2,1862.5 h50
  text "5" at 1146.85,1861.24 h50
  text "43" at 1567.45,1861.65 h50
  text "44" at 1666.85,1861.3 h50
  text "8" at 751.85,1860.75 h50
  text "9" at 851.85,1860.75 h50
  text "12" at 2729.25,1858.6 h50
  text "36" at 2827.4,1858.6 h50
  text "39" at 3121.3,1857.75 h50
  text "25" at 3422.6,1857.75 h50
  text "38" at 3023.1,1856.95 h50
  text "40" at 3222,1856.95 h50
  text "37" at 2921.55,1855.25 h50
  text "27" at 3321.05,1856.1 h50
  text "18" at 3631.75,1798.45 h50
  text "15" at 3908.05,1797.6 h50
  text "14" at 3907.2,1699.4 h50
  text "19" at 3631.75,1698.55 h50
  text "VDD_PS" at 239,1620.49 h50 r90
  text "VDD_PS" at 339,1620.49 h50 r90
  text "VDD_PS" at 140.2,1618.9 h50 r90
  text "GND" at 438.95,1618.05 h50 r90
  text "GND" at 3640.05,1597.85 h50
  text "17" at 3906.4,1597.05 h50
  text "NRST" at 3945,1497.5 h50
  text "GND" at 3640,1496 h50
  text "VDD" at 2740,1297.5 h50
  text "1" at 2431.6,1293.05 h50
  text "2" at 2700.4,1199.85 h50
  text "0" at 2429.95,1199 h50
  text "NRST" at 2451.55,1098.3 h50
  text "GND" at 2741.2,1096.65 h50
  text "VDD" at 3546.15,1049.66 h50
  text "GND" at 3835,1047.5 h50
  text "4" at 2431.6,999.25 h50
  text "3" at 2700.4,998.4 h50
  text "VDD" at 3546.15,951 h50
  text "GND" at 3835,947.5 h50
  text "VDD_EXP" at 143.4,858.25 h50 r90
  text "24" at 3806.45,855.5 h50
  text "41" at 3532.65,850.5 h50
  text "AT_3.3V" at 343.35,832.1 h50 r90
  text "5V_USB" at 240.1,824.3 h50 r90
  text "GND" at 438.7,755.03 h50 r90
  text "21" at 3531.8,750.65 h50
  text "20" at 3807.3,750.65 h50
  text "NRST" at 1301.35,516.45 h50 r90
  text "GND" at 1714.25,502.1 h50 r90
  text "GND" at 1611,500.8 h50 r90
  text "VDD" at 1415,495.55 h50 r90
  text "VDD" at 1117.1,494.25 h50 r90
  text "VDD" at 1215.1,494.25 h50 r90
  text "VIN" at 1813.55,486.4 h50 r90
  text "5V_USB" at 241.4,481 h50 r90
  text "VDD_PS" at 142.1,479.7 h50 r90
  text "AT_3.3V" at 340.7,478.4 h50 r90
  text "GND" at 440.05,478.4 h50 r90
  text "5V" at 1515.65,469.4 h50 r90
  text "13" at 2025.3,453.05 h50
  text "29" at 2118.7,452.2 h50
  text "11" at 2218.6,452.2 h50
  text "32" at 2420.2,452.3 h50
  text "33" at 2518.8,452.3 h50
  text "31" at 2317.4,451.75 h50
  text "34" at 2619.55,451.75 h50
  text "35" at 2720.3,452.05 h50
  text "ANDROMEDA" at 3928,20 h62.99
Mechanical 1:
  lines w5: -0.01,2288.83 cw(c110.84,2288.83) 110.84,2399.68 ; -0.01,2300 0.15,108.68 ccw(c110.99,108.68) 110.99,-2.17 3939.15,-2.01 ccw(c3939.15,108.83) 4049.99,108.83 4049.83,2286.99 ccw(c3938.99,2286.99) 3938.99,2397.83 ; 110.84,2400 3938.99,2400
